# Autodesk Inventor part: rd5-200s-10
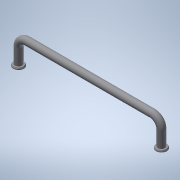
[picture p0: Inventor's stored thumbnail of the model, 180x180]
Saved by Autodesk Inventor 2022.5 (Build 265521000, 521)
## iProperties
Created: 2016-12
Part Number: rd5-200s-10
Material: 一般
Document SubType Name: Modeling
Designer: imaocorp
Density: 1 g/cm^3
Appearance: 既定
Author: imaocorp
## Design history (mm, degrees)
node "rd5-200s-10.x_t1"
node "rd5-200s-10"
node "Base1"
